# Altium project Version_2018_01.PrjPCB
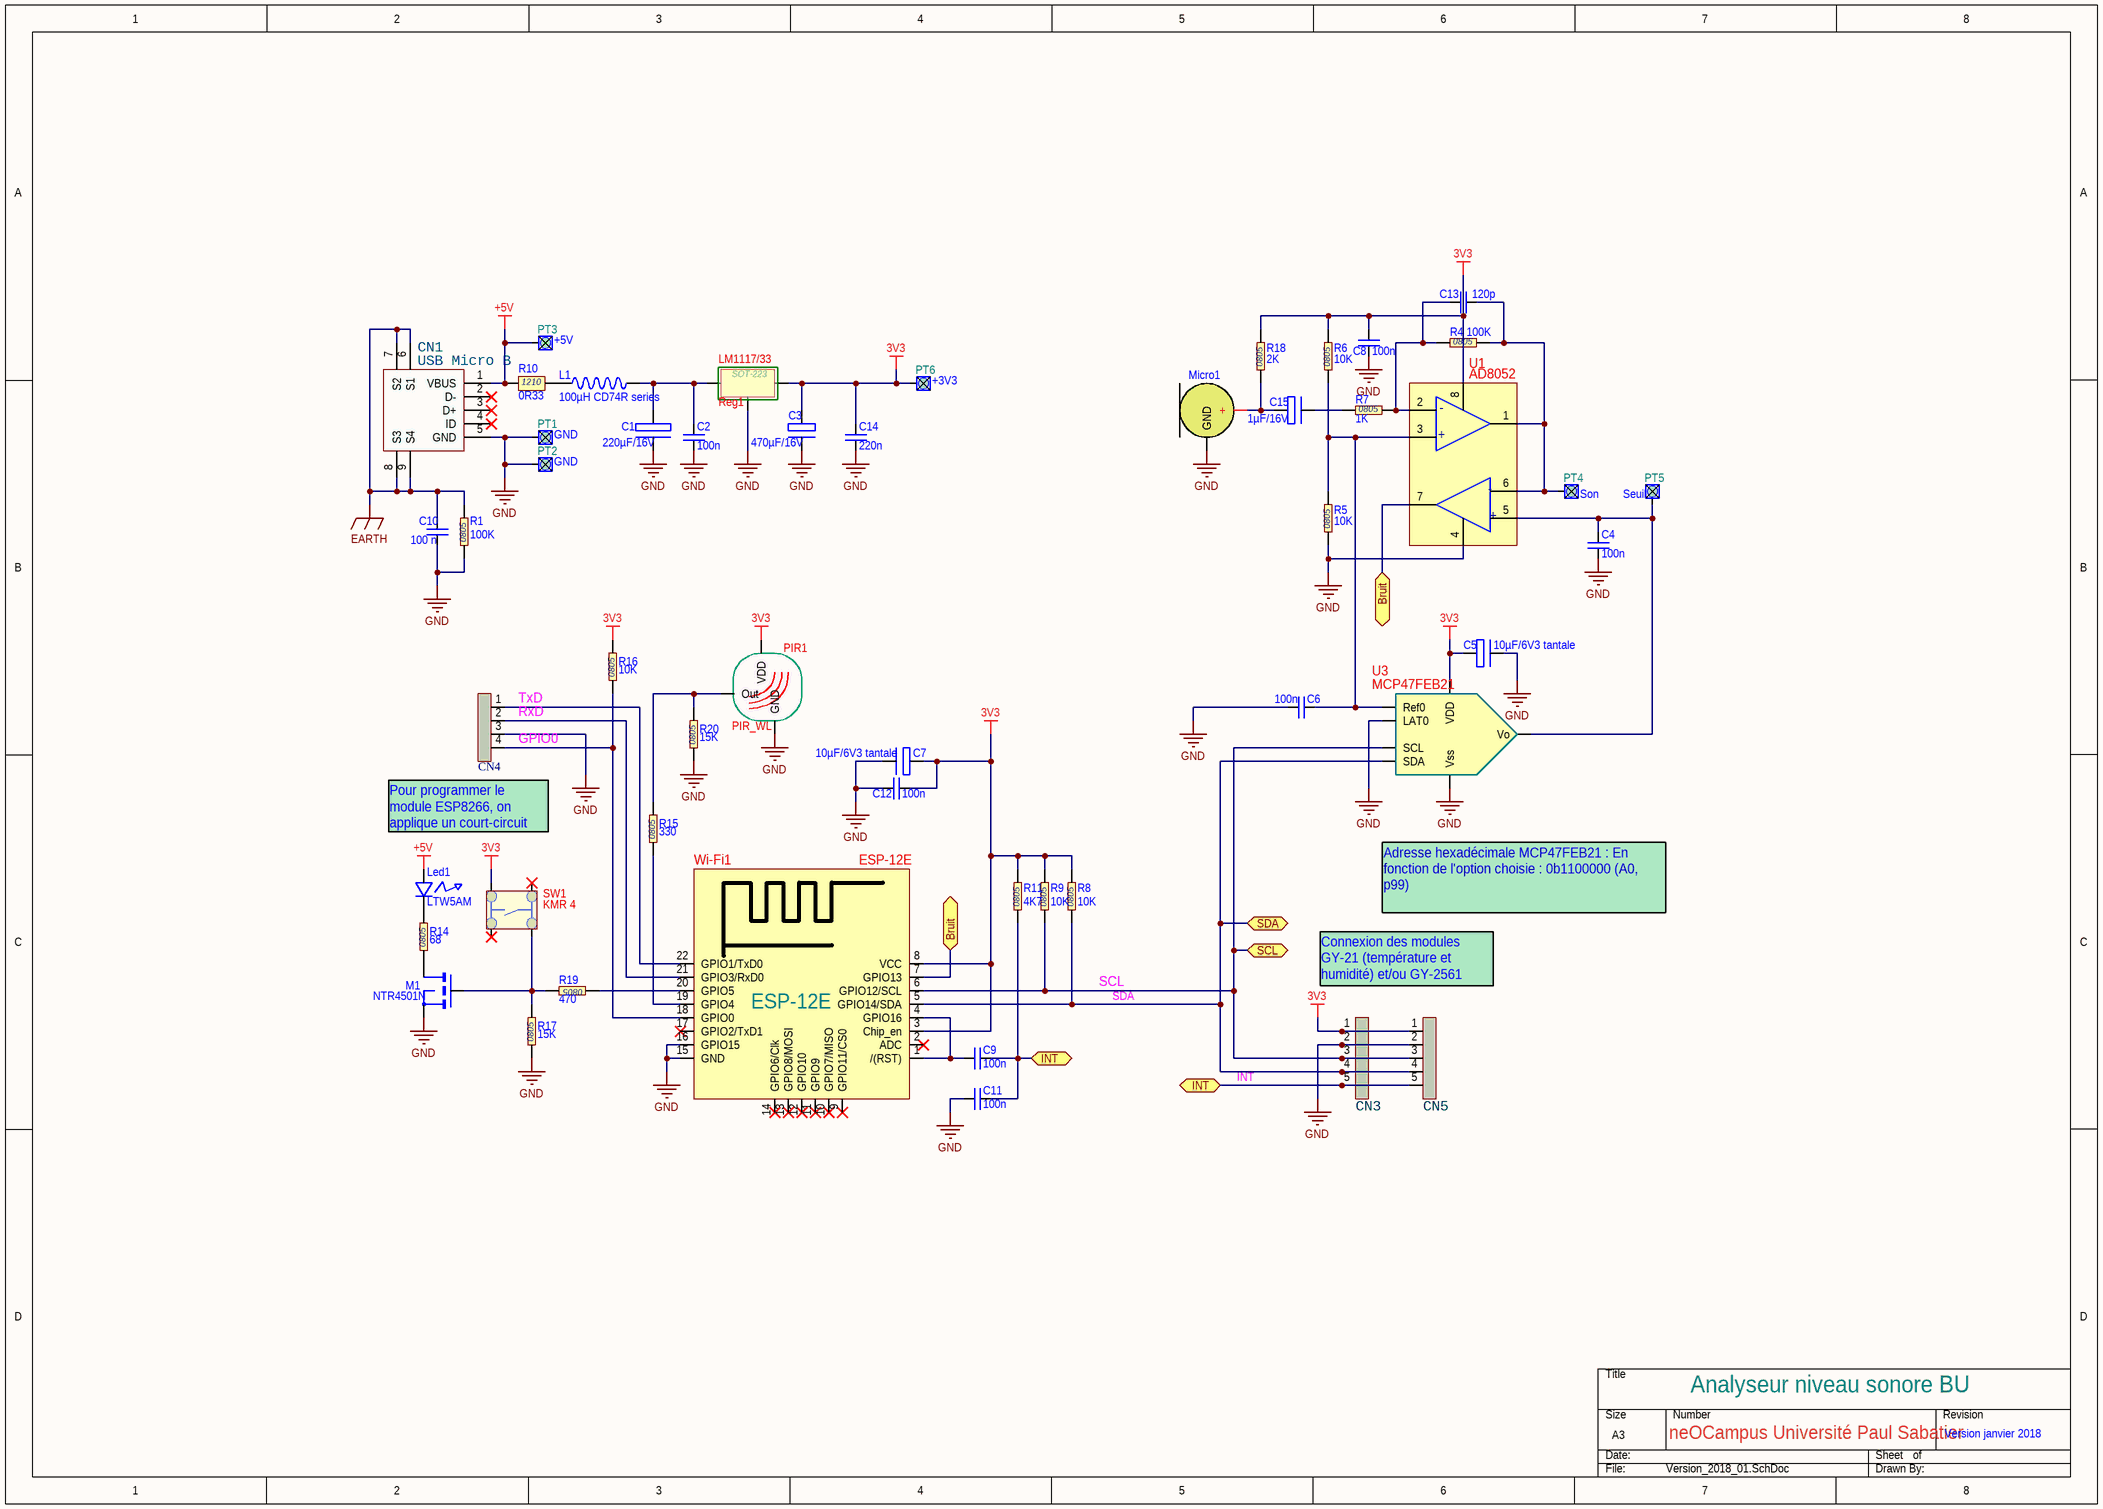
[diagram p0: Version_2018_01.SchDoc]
1 sheet, 51 parts. Net scope: flat (ports and power ports of the same name join across sheets).
Board files: Version_2018_01.PcbDoc, Pannelisation_01.PcbDoc

## Sheet Version_2018_01.SchDoc
size A3

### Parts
C1  220µF/16V  [7343-31]
C2  100n  [0805]
C3  470µF/16V  [47µF/16V]
C4  100n  [0805]
C5  10µF/6V3 tantale  [Tantale 10µF/6V3]
C6  100n  [0805]
C7  10µF/6V3 tantale  [Tantale 10µF/6V3]
C8  100n  [0805]
C9  100n  [0805]
C10  100 n  [0805]
C11  100n  [0805]
C12  100n  [0805]
C13  120p  [0805]
C14  220n  [0805]
C15  1µF/16V  [3216-18]
CN1  USB Micro B  [USB Micro 714-2347]
CN3  inch_ligne 1x5  [INCH_1x5_droit]  (value not drawn)
CN4  inch_ligne 1x4  [INCH_1x4_droit]  (value not drawn)
CN5  inch_ligne 1x5  [INCH_1x5_droit]  (value not drawn)
L1  100µH CD74R series  [SELF CD74R]
Led1  LTW5AM  [LTW5AM]
M1  NTR4501N  [SOT23 (NTR4501)]
Micro1  Electret  [Micro_electret simple]  (value not drawn)
PIR1  PIR_WL  [PIR_WL]
PT1  GND  [PTEST boucle]
PT2  GND  [PTEST boucle]
PT3  +5V  [PTEST boucle]
PT4  Son  [PTEST boucle]
PT5  Seuil  [PTEST boucle]
PT6  +3V3  [PTEST boucle]
R1  100K  [0805]
R4  100K  [0805]
R5  10K  [0805]
R6  10K  [0805]
R7  1K  [0805]
R8  10K  [0805]
R9  10K  [0805]
R10  0R33  [1210]
R11  4K7  [0805]
R14  68  [0805]
R15  330  [0805]
R16  10K  [0805]
R17  15K  [0805]
R18  2K  [0805]
R19  470  [0805]
R20  15K  [0805]
Reg1  LM1117/33  [SOT-223 thermo1]
SW1  KMR 4  [µSwitch KMR4]
U1  AD8052  [SOIC08]
U3  MCP47FEB21  [TSSOP_8]
Wi-Fi1  ESP-12E  [ESP-12E]

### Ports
Bruit, INT, SCL, SDA

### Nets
3V3: C3.1(V+) C5.1(V+) C7.1(V+) C8.2(CT2) C12.2(CT2) C14.2(CT2) CN3.1 CN5.1 PIR1.1(VDD) PT6.1(PIN) R6.2(CT2) R8.2(CT2) R9.2(CT2) R11.2(CT2) R16.2(CT2) R18.2(CT2) Reg1.2(OUT) SW1.2(CT2) U1.8(V+) U3.1(VDD) Wi-Fi1.3(Chip_en) Wi-Fi1.8(VCC)
+5V: CN1.1(VBUS) Led1.1(anode) PT3.1(PIN) R10.1(CT1)
EARTH: C10.2(CT2) CN1.6(S1) CN1.7(S2) CN1.8(S3) CN1.9(S4) R1.2(CT2)
GND: C1.2(V-) C2.1(CT1) C3.2(V-) C4.1(CT1) C5.2(V-) C6.2(CT2) C7.2(V-) C8.1(CT1) C10.1(CT1) C11.1(CT1) C12.1(CT1) C14.1(CT1) CN1.5(GND) CN3.2 CN4.3 CN5.2 M1.3(S) Micro1.0(GND) PIR1.3(GND) PT1.1(PIN) PT2.1(PIN) R1.1(CT1) R5.1(CT1) R17.1(CT1) R20.1(CT1) Reg1.1(GND) U1.4(V-) U3.5(Vss) U3.6(LAT0) Wi-Fi1.15(GND) Wi-Fi1.16(GPIO15)
GPIO0: CN4.4 R16.1(CT1) Wi-Fi1.18(GPIO0)
INT: C9.1(CT1) C11.2(CT2) CN3.5 CN5.5 R11.1(CT1) ; port INT
RxD: CN4.2 Wi-Fi1.21(GPIO3/RxD0)
SCL: CN3.3 CN5.3 R9.1(CT1) U3.7(SCL) Wi-Fi1.6(GPIO12/SCL) ; port SCL
SDA: CN3.4 CN5.4 R8.1(CT1) U3.8(SDA) Wi-Fi1.5(GPIO14/SDA) ; port SDA
TxD: CN4.1 Wi-Fi1.22(GPIO1/TxD0)
NetC1_1: C1.1(V+) C2.2(CT2) L1.1(CT1) Reg1.3(IN)
NetC4_2: C4.2(CT2) PT5.1(PIN) U1.5(in+) U3.3(Vo)
NetC6_1: C6.1(CT1) R5.2(CT2) R6.1(CT1) U1.3(in+) U3.2(Ref0)
NetC9_2: C9.2(CT2) Wi-Fi1.1(/(RST)) Wi-Fi1.4(GPIO16)
NetC13_1: C13.1(CT1) R4.1(CT1) R7.2(CT2) U1.2(in-)
NetC13_2: C13.2(CT2) PT4.1(PIN) R4.2(CT2) U1.1(out) U1.6(in-)
NetC15_1: C15.1(V+) Micro1.1(+) R18.1(CT1)
NetC15_2: C15.2(V-) R7.1(CT1)
NetL1_2: L1.2(CT2) R10.2(CT2)
NetLed1_2: Led1.2(cathode) R14.2(CT2)
NetM1_1: M1.1(D) R14.1(CT1)
NetM1_2: M1.2(G) R17.2(CT2) R19.2(CT2) SW1.3(CT3)
NetPIR1_2: PIR1.2(Out) R15.2(CT2) R20.2(CT2)
NetR15_1: R15.1(CT1) Wi-Fi1.19(GPIO4)
NetR19_1: R19.1(CT1) Wi-Fi1.20(GPIO5)
NetU1_7: U1.7(out) Wi-Fi1.7(GPIO13) ; port Bruit

Not connected (* = marked no-connect by the designer): CN1 2(D-)* 3(D+)* 4(ID)*; SW1 1(CT1)* 4(CT4)*; Wi-Fi1 2(ADC)* 9(GPIO11/CS0)* 10(GPIO7/MISO)* 11(GPIO9)* 12(GPIO10)* 13(GPIO8/MOSI)* 14(GPIO6/Clk)* 17(GPIO2/TxD1)*

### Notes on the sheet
- Pour programmer le module ESP8266, on applique un court-circuit entre 3 et 4.
- Adresse hexadécimale MCP47FEB21 : En fonction de l'option choisie : 0b1100000 (A0, p99)
  Adresse hexadécimale MCP9808 : 0x3_
- Connexion des modules GY-21 (température et humidité) et/ou GY-2561 (Luxmètre)
- Analyseur niveau sonore BU
- neOCampus Université Paul Sabatier
- Version janvier 2018

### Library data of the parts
C1 = tantale 220µF/16V: 253-5290 case 7343-31
C2 C4 C6 C8-C14 = Cap_CMS_0805: CMS 0805
C3 = 47µF/16V: électrochimique diam. 6,3mm 128-1810
C5 C7 = tantale 10µF/6V3: 175-4041 ou 145-7412 case 3216-18
C15 = tantale 1µF/16V: 145-7406 case 3216-18
CN1 = USB Micro B: Amphenol 714-2347
CN3 CN5 = Inch_1x5_droit
CN4 = Inch_1x4_droit
L1 = Self CD74R: SMT CD74R Aliexpress
Led1 = LTW5AM LED: LED Golden Dragon Plus
M1 = NTR4501N: MOSFET canal N
Micro1 = Microphone_03: Microphone électret
PIR1 = PIR_01: Détecteur infrarouge
PT1-PT6 = PTEST boucle: pointe de test CI 262-2179
R1 R4-R9 R11 R14-R20 = Res CMS 0805: CMS 0805
R10 = Res CMS 1210 ERJ14B: CMS 1210
Reg1 = LM1117MPX-3.3: Régulateur SOT-223
SW1 = µSwitch: KMR 4 Series 793-1605
U1 = AD8052: AOP
U3 = MCP47FEB21: DAC I2C (RS : 879-3261)
Wi-Fi1 = ESP-12E: ESP-12E module Wi-Fi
